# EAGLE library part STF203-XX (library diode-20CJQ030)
SEMTECH's STF203-xx USB Upstream Port Filter and TVS For EMI Filtering and ESD Protection The STF203 is a combination EMI filter and line termination device with integrated TVS diodes for use on upstream USB ports. It is constructed using a proprietary technology that allows passive components and TVS diodes to be integrated in the same package. Each device will provide termination, filtering, and ESD protection for one upstream USB port. The STF203 is an easily implemented solution for meeting the requirements of revision 1.1 of the Universal Serial Bus specification. Line termination is achieved with series resistors on both the D+ and D- USB lines. The value of series resistance added to the output impedance of the USB driver must be as close to possible to the 45 Ohm characteristic impedance of the cable (90Ohm balanced) to minimize transmission line reflections. They are available with resistor values of 15Ohm (STF203-15), 22Ohm (STF203-22), and 33Ohm (STF203-33). The 1.5kOhm pull-up resistor is required by the USB specification to identify the equipment as either a full-speed (connected to D+ line) or low-speed (connected to Dline) device. The 47pF capacitors are required to bypass high frequency energy to ground and to control the edge rate of the USB signals. The TVS diodes provide ESD protection of both (D+ and D-) data lines and the voltage bus (VBUS). The TVS diodes on the input/output pins provide suppression of ESD voltages in excess of ±15kV (air discharge) and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
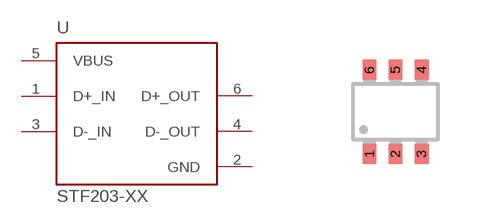
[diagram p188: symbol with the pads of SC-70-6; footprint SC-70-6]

Designator prefix U

## STF203-XX  [SC-70-6]
1  D+_IN  pas
2  GND  pas
3  D-_IN  pas
4  D-_OUT  pas
5  VBUS  pas
6  D+_OUT  pas

## Footprint SC-70-6 (pad centres in mm)
Texas Instruments Package SC-70-6 (-DCK)
smd 0.35 x 0.5: 1 -0.65,-1.05; 2 0,-1.05; 3 0.65,-1.05; 4 0.65,1.05; 5 0,1.05; 6 -0.65,1.05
